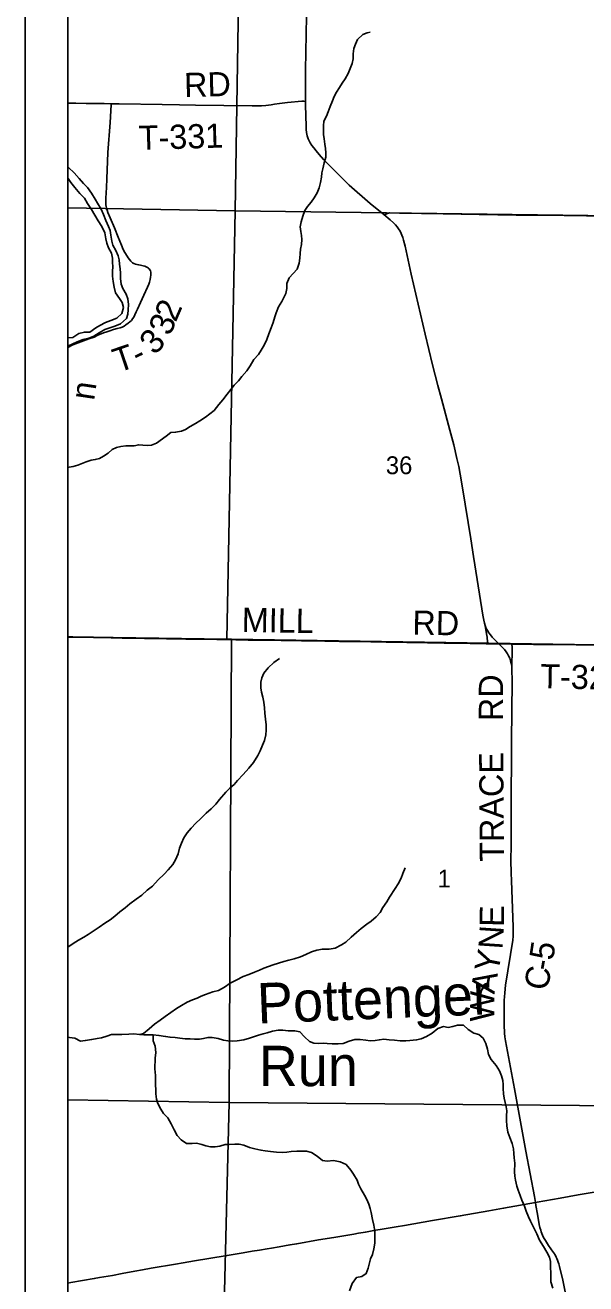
# Model space of a CAD drawing. Extents: x 0 to 34, y 0 to 22.
# Drawn here: x 2 to 3.317, y 16.874 to 19.83 of the extents above; entities that cross this region are included whole.
import ezdxf

# ---------------------------------------------------------------- set-up
doc = ezdxf.new("R2010")
doc.units = 0
for name, color, linetype in [('GM_X_Corporation', 7, 'Continuous'), ('GM_X_County_Road', 7, 'Continuous'), ('GM_X_County_Road_Text', 7, 'Continuous'), ('GM_X_Major_River', 7, 'Continuous'), ('GM_X_Minor_River', 7, 'Continuous'), ('GM_X_Minor_River_Text', 7, 'Continuous'), ('GM_X_Rail_Line_Text', 7, 'Continuous'), ('GM_X_Section_Text', 7, 'Continuous'), ('GM_X_State_Location', 7, 'Continuous'), ('GM_X_State_Route', 7, 'Continuous'), ('GM_X_Township_Road', 7, 'Continuous'), ('GM_X_Township_Road_Text', 7, 'Continuous'), ('SH_Data', 7, 'Continuous')]:
    doc.layers.add(name, color=color, linetype=linetype)

msp = doc.modelspace()

# ---------------------------------------------------------------- linework, layer by layer
at = {"layer": 'GM_X_Corporation'}
for points in [[(2.1, 20.9), (2.1, 18.3932), (2.1117, 18.393), (2.1602, 18.3922), (2.202, 18.3914), (2.2273, 18.3909), (2.2553, 18.3907), (2.2801, 18.3902), (2.3025, 18.3898), (2.3317, 18.3894), (2.377, 18.3886), (2.423, 18.388), (2.4497, 18.3877), (2.4944, 18.3869), (2.5236, 18.3864), (2.5653, 18.3858), (2.6013, 18.3852), (2.6162, 18.385), (2.6485, 18.3844), (2.7038, 18.3834), (2.738, 18.3831), (2.7746, 18.3825), (2.8113, 18.382), (2.8473, 18.3816), (2.9443, 18.38), (2.9834, 18.3794), (3.0068, 18.379), (3.0451, 18.3784), (3.0716, 18.3779), (3.0834, 18.3777), (3.0859, 18.3777), (3.0906, 18.3777), (3.0991, 18.3776), (3.1035, 18.3775), (3.1121, 18.3774), (3.1429, 18.3768), (3.1537, 18.3767), (3.1933, 18.3762), (3.2311, 18.3758), (3.3557, 18.374)], [(3.3557, 18.374), (3.2311, 18.3758), (3.1933, 18.3762), (3.1537, 18.3767), (3.1429, 18.3768), (3.1121, 18.3774), (3.1035, 18.3775), (3.0991, 18.3776), (3.0906, 18.3777), (3.0859, 18.3777), (3.0834, 18.3777), (3.0716, 18.3779), (3.0451, 18.3784), (3.0068, 18.379), (2.9834, 18.3794), (2.9443, 18.38), (2.8473, 18.3816), (2.8113, 18.382), (2.7746, 18.3825), (2.738, 18.3831), (2.7038, 18.3834), (2.6485, 18.3844), (2.6162, 18.385), (2.6013, 18.3852), (2.5653, 18.3858), (2.5236, 18.3864), (2.4944, 18.3869), (2.4497, 18.3877), (2.423, 18.388), (2.377, 18.3886), (2.3317, 18.3894), (2.3025, 18.3898), (2.2801, 18.3902), (2.2553, 18.3907), (2.2273, 18.3909), (2.202, 18.3914), (2.1602, 18.3922), (2.1117, 18.393), (2.1, 18.3932), (2.1, 14.1)]]:
    msp.add_lwpolyline(points, dxfattribs=at)
for points in [[(2.1, 20.3889), (2.1, 19.4012), (2.4933, 19.3936), (2.5086, 20.3801)], [(2.5086, 20.3801), (3.5147, 20.359), (3.4987, 19.3808), (2.4933, 19.3936)], [(2.1, 19.4012), (2.1, 18.3932), (2.4733, 18.3879), (2.4933, 19.3936)], [(3.4987, 19.3808), (3.4912, 18.3726), (2.4847, 18.3876), (2.4733, 18.3879), (2.4933, 19.3936)], [(2.1, 18.3932), (2.1, 17.3057), (2.4791, 17.2994), (2.4847, 18.3876), (2.4733, 18.3879)], [(2.4847, 18.3876), (3.4912, 18.3726), (3.4847, 17.2912), (2.4791, 17.2994)], [(2.1, 17.3057), (2.1, 16.3195), (2.4544, 16.3158), (2.4791, 17.2994)], [(3.4847, 17.2912), (3.4681, 16.2816), (2.4544, 16.3158), (2.4791, 17.2994)]]:
    msp.add_lwpolyline(points, close=True, dxfattribs=at)
at = {"layer": 'GM_X_County_Road'}
for points in [[(3.1124, 18.3769), (3.1011, 18.388), (3.0965, 18.3929), (3.0927, 18.3977), (3.0891, 18.4027), (3.0855, 18.4085), (3.0829, 18.4133), (3.0803, 18.4203), (3.0787, 18.4255), (3.077, 18.4327), (3.0749, 18.4442), (3.067, 18.4939), (3.0531, 18.5823), (3.0469, 18.6232), (3.027, 18.7437), (3.0214, 18.7754), (3.0183, 18.7933), (3.014, 18.8126), (3.0064, 18.8441), (2.9976, 18.879), (2.978, 18.9523), (2.9693, 18.9834), (2.9566, 19.0321), (2.9478, 19.0679), (2.939, 19.1045), (2.9063, 19.2455), (2.892, 19.311), (2.8885, 19.3249), (2.8866, 19.3316), (2.8847, 19.3369), (2.883, 19.3409), (2.8804, 19.3459), (2.8768, 19.3519), (2.8735, 19.3565), (2.8695, 19.3613), (2.8651, 19.3657), (2.8571, 19.3727), (2.842, 19.385), (2.8098, 19.4111), (2.7608, 19.454), (2.7006, 19.5149), (2.6907, 19.5261), (2.6835, 19.5346), (2.6777, 19.5419), (2.6734, 19.5478), (2.6693, 19.554), (2.6662, 19.56), (2.6648, 19.5633), (2.6624, 19.5703), (2.6607, 19.5781), (2.66, 19.5848), (2.6595, 19.5922), (2.6587, 19.6431), (2.6585, 19.6511), (2.6584, 19.6599), (2.6586, 19.7245), (2.6603, 19.8512)], [(2.1, 18.3927), (2.112, 18.3925), (2.1604, 18.3916), (2.2022, 18.3908), (2.2275, 18.3904), (2.2555, 18.3902), (2.2804, 18.3897), (2.3027, 18.3893), (2.3319, 18.3889), (2.3773, 18.3881), (2.4232, 18.3875), (2.4499, 18.3871), (2.4947, 18.3864), (2.5239, 18.3859), (2.5655, 18.3853), (2.6015, 18.3847), (2.6164, 18.3845), (2.6488, 18.3839), (2.704, 18.3829), (2.7382, 18.3826), (2.7749, 18.382), (2.8115, 18.3815), (2.8476, 18.3811), (2.9445, 18.3794), (2.9836, 18.3788), (3.007, 18.3785), (3.0453, 18.3778), (3.0718, 18.3774), (3.0826, 18.3772), (3.0861, 18.3772), (3.0908, 18.3771), (3.0993, 18.3771), (3.1124, 18.3769)], [(3.2703, 16.8429), (3.2623, 16.8819), (3.2545, 16.9144), (3.2531, 16.9203), (3.2517, 16.9248), (3.2503, 16.929), (3.2486, 16.9332), (3.2471, 16.9364), (3.2452, 16.9401), (3.2439, 16.9423), (3.2427, 16.9445), (3.2416, 16.9462), (3.2402, 16.9484), (3.2292, 16.9638), (3.2216, 16.9753), (3.2188, 16.9799), (3.2167, 16.9837), (3.2146, 16.9879), (3.2131, 16.9919), (3.2118, 16.9956), (3.2106, 16.9995), (3.209, 17.0062), (3.2074, 17.0127), (3.203, 17.0376), (3.1995, 17.0579), (3.1984, 17.0647), (3.196, 17.0787), (3.1755, 17.1856), (3.149, 17.3316), (3.1279, 17.4442), (3.1266, 17.4537), (3.1256, 17.4624), (3.125, 17.482), (3.1248, 17.5402), (3.1253, 17.5481), (3.1261, 17.5568), (3.1282, 17.575), (3.1452, 17.6807), (3.146, 17.6901), (3.1463, 17.6995), (3.146, 17.7112), (3.1452, 17.7342), (3.1419, 17.82), (3.1412, 17.8391), (3.1407, 17.8678), (3.1411, 17.9038), (3.1416, 17.9795), (3.1424, 18.149), (3.1434, 18.2887), (3.1432, 18.318), (3.1429, 18.3257), (3.1416, 18.3313), (3.14, 18.3366), (3.1379, 18.3431), (3.1354, 18.3484), (3.1325, 18.3536), (3.1295, 18.358), (3.1255, 18.3633), (3.1213, 18.3682), (3.1124, 18.3769)]]:
    msp.add_lwpolyline(points, dxfattribs=at)
at = {"layer": 'GM_X_Major_River'}
for points in [[(2.1782, 19.3978), (2.1702, 19.412), (2.1644, 19.4216), (2.1556, 19.4355), (2.1465, 19.449), (2.1369, 19.4584), (2.1269, 19.47), (2.1151, 19.4836), (2.1018, 19.496), (2.1, 19.4973)], [(2.1, 19.4711), (2.1011, 19.4699), (2.1073, 19.4602), (2.1165, 19.4486), (2.1283, 19.435), (2.1394, 19.4234), (2.1467, 19.4111), (2.1555, 19.3972), (2.1638, 19.3837), (2.1715, 19.3702), (2.1802, 19.3571), (2.1867, 19.3422), (2.1898, 19.328), (2.1914, 19.3178), (2.1953, 19.3074), (2.2026, 19.2947), (2.2049, 19.2829), (2.2054, 19.2726), (2.206, 19.2631), (2.2049, 19.2518), (2.205, 19.2404), (2.207, 19.2282), (2.2086, 19.2149), (2.212, 19.2011), (2.2219, 19.1884), (2.2281, 19.1788), (2.2309, 19.1669), (2.2271, 19.1526), (2.2151, 19.1419), (2.2009, 19.1365), (2.1887, 19.1315), (2.1756, 19.125), (2.166, 19.1192), (2.1521, 19.1093), (2.1392, 19.1092), (2.1262, 19.1057), (2.1119, 19.0962), (2.1, 19.0956)], [(2.1, 19.0756), (2.1, 19.0757), (2.1123, 19.0818), (2.1223, 19.0861), (2.1365, 19.0918), (2.1498, 19.0945), (2.1613, 19.0996), (2.1737, 19.1076), (2.1871, 19.1153), (2.2009, 19.1202), (2.2108, 19.1234), (2.2239, 19.1288), (2.2378, 19.1413), (2.2407, 19.1511), (2.2421, 19.1617), (2.2428, 19.1742), (2.2409, 19.1872), (2.2373, 19.1979), (2.2293, 19.2117), (2.2251, 19.2221), (2.2242, 19.2354), (2.2238, 19.2479), (2.2233, 19.2574), (2.2217, 19.2688), (2.2204, 19.2791), (2.2187, 19.2886), (2.2126, 19.3005), (2.2061, 19.3132), (2.2037, 19.3228), (2.2014, 19.3369), (2.1994, 19.3479), (2.1958, 19.3575), (2.1897, 19.3709), (2.184, 19.3851), (2.1782, 19.3978)]]:
    msp.add_lwpolyline(points, dxfattribs=at)
at = {"layer": 'GM_X_Minor_River'}
for points in [[(2.6957, 19.473), (2.697, 19.4829), (2.6991, 19.4927), (2.7024, 19.5067), (2.7057, 19.5203), (2.7062, 19.5305), (2.7049, 19.54), (2.704, 19.5503), (2.7023, 19.5632), (2.7006, 19.5735), (2.7004, 19.5837), (2.7006, 19.594), (2.7015, 19.6042), (2.7078, 19.6162), (2.7118, 19.6268), (2.7166, 19.6388), (2.7218, 19.6524), (2.7258, 19.6622), (2.7313, 19.6727), (2.7383, 19.684), (2.7445, 19.6937), (2.7516, 19.7039), (2.7586, 19.7166), (2.7634, 19.7283), (2.7678, 19.7404), (2.7699, 19.7513), (2.7705, 19.7627), (2.7722, 19.7756), (2.7758, 19.7858), (2.7802, 19.7967), (2.7929, 19.8082), (2.8033, 19.8118), (2.8101, 19.8136)], [(2.1, 18.791), (2.1034, 18.7917), (2.1129, 18.7931), (2.124, 18.7967), (2.1431, 18.8043), (2.1549, 18.8086), (2.1644, 18.8096), (2.1747, 18.8124), (2.1843, 18.8176), (2.1947, 18.8246), (2.2043, 18.8331), (2.2143, 18.8382), (2.2249, 18.8403), (2.236, 18.8416), (2.2458, 18.8418), (2.2557, 18.8416), (2.2668, 18.8445), (2.2762, 18.8439), (2.2872, 18.8426), (2.2967, 18.8432), (2.3082, 18.8479), (2.3313, 18.8649), (2.3424, 18.8734), (2.3534, 18.874), (2.3668, 18.8764), (2.3763, 18.8804), (2.3878, 18.8874), (2.4001, 18.8947), (2.4105, 18.9006), (2.4235, 18.9091), (2.4339, 18.9169), (2.4435, 18.925), (2.4544, 18.9392), (2.4645, 18.9504), (2.4746, 18.9635), (2.4828, 18.974), (2.4905, 18.9841), (2.5006, 18.9949), (2.5087, 19.0046), (2.5204, 19.018), (2.5286, 19.03), (2.5372, 19.0447), (2.5476, 19.0566), (2.5543, 19.0663), (2.5613, 19.0787), (2.5676, 19.0915), (2.5721, 19.1047), (2.578, 19.119), (2.5824, 19.1318), (2.5861, 19.1446), (2.5893, 19.1544), (2.5952, 19.1684), (2.6027, 19.1811), (2.6121, 19.1995), (2.6142, 19.2116), (2.6148, 19.2234), (2.62, 19.2362), (2.6297, 19.2466), (2.639, 19.2567), (2.6434, 19.271), (2.6448, 19.2831), (2.6457, 19.2941), (2.6467, 19.304), (2.6491, 19.3145), (2.6501, 19.3267), (2.6488, 19.3362), (2.6471, 19.3457), (2.6457, 19.3563), (2.6482, 19.3684), (2.6523, 19.3816), (2.6571, 19.3944), (2.6633, 19.4042), (2.6715, 19.4147), (2.6785, 19.4248), (2.6859, 19.4364), (2.6903, 19.4481), (2.6932, 19.4606), (2.6957, 19.473)], [(2.1, 17.664), (2.1005, 17.6643), (2.1125, 17.6728), (2.1256, 17.6812), (2.1379, 17.6877), (2.1479, 17.6939), (2.1599, 17.7019), (2.1738, 17.7115), (2.1873, 17.7206), (2.1993, 17.729), (2.2105, 17.7375), (2.2225, 17.7471), (2.2345, 17.757), (2.2457, 17.7666), (2.2608, 17.7772), (2.2743, 17.7864), (2.2867, 17.7982), (2.2987, 17.8074), (2.3123, 17.8222), (2.3267, 17.8359), (2.3357, 17.8459), (2.3466, 17.8589), (2.3533, 17.8698), (2.359, 17.884), (2.3627, 17.8972), (2.3672, 17.9089), (2.3728, 17.9216), (2.3807, 17.9332), (2.3901, 17.944), (2.401, 17.9555), (2.4119, 17.9658), (2.4251, 17.9795), (2.4371, 17.9895), (2.4476, 18.0002), (2.4566, 18.0114), (2.4711, 18.0285), (2.4808, 18.0377), (2.4905, 18.0462), (2.4987, 18.0558), (2.5116, 18.0699), (2.5256, 18.0848), (2.5362, 18.0982), (2.5461, 18.115), (2.552, 18.1255), (2.5577, 18.139), (2.5621, 18.1499), (2.5655, 18.1631), (2.5661, 18.174), (2.5657, 18.1869), (2.5645, 18.2002), (2.5629, 18.2143), (2.5621, 18.2265), (2.5605, 18.2398), (2.5578, 18.252), (2.5551, 18.2631), (2.5538, 18.2737), (2.5534, 18.287), (2.5555, 18.2968), (2.5607, 18.3081), (2.5709, 18.3207), (2.5841, 18.3333), (2.5972, 18.3428)], [(2.2688, 17.4596), (2.2779, 17.4616), (2.2911, 17.4723), (2.3035, 17.4834), (2.317, 17.4933), (2.329, 17.5014), (2.3421, 17.5113), (2.3553, 17.5204), (2.3672, 17.5277), (2.3803, 17.535), (2.3929, 17.5411), (2.4037, 17.545), (2.4136, 17.5493), (2.4236, 17.5529), (2.4404, 17.5593), (2.4542, 17.5628), (2.468, 17.5708), (2.4811, 17.5799), (2.4954, 17.5872), (2.5123, 17.5955), (2.5249, 17.6001), (2.5383, 17.6055), (2.5502, 17.6105), (2.5605, 17.6148), (2.5716, 17.619), (2.5827, 17.6226), (2.5946, 17.6268), (2.6072, 17.6311), (2.619, 17.6338), (2.632, 17.6373), (2.6465, 17.6419), (2.6592, 17.6472), (2.6723, 17.6538), (2.6849, 17.6576), (2.6982, 17.6599), (2.7141, 17.6599), (2.7278, 17.6619), (2.7428, 17.6702), (2.7532, 17.676), (2.7657, 17.6879), (2.7784, 17.6989), (2.7893, 17.7082), (2.8024, 17.7185), (2.8125, 17.7254), (2.8241, 17.7357), (2.8338, 17.7457), (2.8402, 17.7577), (2.8497, 17.7711), (2.8556, 17.782), (2.869, 17.8022), (2.8757, 17.8134), (2.8829, 17.8268), (2.8866, 17.8374), (2.8926, 17.8505)], [(2.4187, 17.4502), (2.4287, 17.4519), (2.4389, 17.452), (2.4533, 17.4498), (2.4661, 17.446), (2.4759, 17.4447), (2.4861, 17.444), (2.4975, 17.4445), (2.5135, 17.4464), (2.5272, 17.451), (2.5383, 17.4549), (2.5479, 17.4577), (2.5586, 17.4605), (2.5685, 17.4632), (2.5811, 17.4671), (2.5945, 17.4691), (2.6051, 17.4692), (2.6179, 17.4677), (2.6331, 17.4681), (2.6452, 17.4659), (2.6559, 17.4535), (2.6674, 17.4426), (2.6779, 17.439), (2.6881, 17.4383), (2.6995, 17.4388), (2.7094, 17.4382), (2.7207, 17.4375), (2.7351, 17.4372), (2.7465, 17.4384), (2.7611, 17.4437), (2.7745, 17.4476), (2.787, 17.4477), (2.7998, 17.4462), (2.8104, 17.4444), (2.8218, 17.4449), (2.8321, 17.4469), (2.842, 17.4482), (2.8545, 17.4471), (2.8673, 17.4457), (2.881, 17.4446), (2.8939, 17.4443), (2.9037, 17.4452), (2.9193, 17.4467), (2.9296, 17.4491), (2.9423, 17.4549), (2.9558, 17.4625), (2.9693, 17.4732), (2.9827, 17.4778), (2.9936, 17.476), (3.0043, 17.4784), (3.0154, 17.4815), (3.0294, 17.4812), (3.0402, 17.471), (3.0536, 17.4624), (3.0653, 17.4594), (3.0753, 17.4508), (3.0822, 17.4382), (3.0861, 17.4248), (3.0884, 17.4126), (3.0942, 17.4007), (3.106, 17.3868), (3.114, 17.3737), (3.1186, 17.3622), (3.1214, 17.3515), (3.1223, 17.3416), (3.1228, 17.3321), (3.1233, 17.32), (3.1249, 17.3097), (3.1269, 17.2998), (3.1293, 17.2895), (3.1314, 17.2799), (3.1303, 17.2686), (3.1304, 17.2576), (3.1313, 17.245), (3.1332, 17.2302), (3.1378, 17.2172), (3.1439, 17.203), (3.1466, 17.1908), (3.1475, 17.1798), (3.1487, 17.1695), (3.1499, 17.1574), (3.1494, 17.1369), (3.1499, 17.1266), (3.1516, 17.1171), (3.1543, 17.1034), (3.1578, 17.0938), (3.1621, 17.0808), (3.166, 17.0701), (3.1725, 17.0559), (3.1763, 17.0445), (3.1821, 17.031), (3.1864, 17.0211), (3.194, 17.0069), (3.2016, 16.9911), (3.208, 16.9766), (3.2175, 16.9615), (3.2251, 16.9481), (3.2313, 16.9362), (3.2333, 16.9259), (3.2337, 16.9122), (3.2342, 16.8997)], [(2.1, 17.4527), (2.104, 17.4522), (2.1168, 17.4504), (2.1303, 17.4436), (2.141, 17.4449), (2.1562, 17.4479), (2.1688, 17.4499), (2.1791, 17.4515), (2.1921, 17.4554), (2.2028, 17.4593), (2.2168, 17.4593), (2.2267, 17.4595), (2.2438, 17.4602), (2.2548, 17.4611), (2.2688, 17.4596), (2.279, 17.4586), (2.2889, 17.4587), (2.3006, 17.4588), (2.3142, 17.4573), (2.3297, 17.4547), (2.3403, 17.4529), (2.3524, 17.4519), (2.3634, 17.4504), (2.3755, 17.4494), (2.3872, 17.4495), (2.3975, 17.4485), (2.4092, 17.4482), (2.4187, 17.4502)], [(2.3006, 17.4588), (2.3007, 17.4448), (2.3053, 17.4321), (2.3068, 17.4169), (2.3053, 17.4037), (2.3047, 17.3783), (2.3058, 17.3627), (2.3063, 17.3532), (2.3064, 17.3407), (2.3065, 17.3297), (2.307, 17.3198), (2.3086, 17.3077), (2.3114, 17.297), (2.3183, 17.2839), (2.3252, 17.2735), (2.3348, 17.2634), (2.3428, 17.2492), (2.35, 17.235), (2.3566, 17.2219), (2.3662, 17.2118), (2.3792, 17.2035), (2.3921, 17.2032), (2.4024, 17.2037), (2.4148, 17.2012), (2.4246, 17.1979), (2.4355, 17.1957), (2.4458, 17.1951), (2.4568, 17.1971), (2.4698, 17.2006), (2.4793, 17.2011), (2.4922, 17.2015), (2.5028, 17.2017), (2.5138, 17.1991), (2.5269, 17.1942), (2.5397, 17.1905), (2.5537, 17.1879), (2.5639, 17.1857), (2.5764, 17.1843), (2.59, 17.1828), (2.6036, 17.1821), (2.6142, 17.1826), (2.6249, 17.1843), (2.6378, 17.1855), (2.6507, 17.1855), (2.661, 17.1849), (2.6723, 17.182), (2.6857, 17.1737), (2.6984, 17.1635), (2.7093, 17.1621), (2.7241, 17.1632), (2.74, 17.1606), (2.7535, 17.1538), (2.7649, 17.141), (2.7711, 17.1314), (2.7795, 17.1175), (2.7831, 17.1076), (2.7885, 17.0968), (2.7972, 17.0818), (2.8026, 17.0714), (2.8069, 17.0611), (2.8101, 17.0508), (2.8125, 17.0412), (2.8159, 17.0245), (2.8186, 17.0111), (2.8209, 16.997), (2.8213, 16.983), (2.821, 16.969), (2.8187, 16.9557), (2.8154, 16.9429), (2.8109, 16.9324), (2.8084, 16.9226), (2.8055, 16.9102), (2.801, 16.8978), (2.791, 16.8912), (2.778, 16.8885), (2.7678, 16.8743), (2.762, 16.857)], [(3.2342, 16.8997), (3.2347, 16.8898), (3.2344, 16.8784), (3.2394, 16.8635)]]:
    msp.add_lwpolyline(points, dxfattribs=at)
at = {"layer": 'GM_X_State_Route'}
msp.add_lwpolyline([(2.1, 16.8755), (2.1076, 16.8768), (2.1621, 16.886), (2.1743, 16.8882), (2.2048, 16.8936), (2.2281, 16.898), (2.2574, 16.9032), (2.2758, 16.9065), (2.296, 16.9101), (2.353, 16.9196), (2.3713, 16.9228), (2.3977, 16.9273), (2.4699, 16.9396), (2.5122, 16.9467), (2.533, 16.9503), (2.5502, 16.9531), (2.5686, 16.9562), (2.5784, 16.9578), (2.5968, 16.9608), (2.6219, 16.965), (2.6378, 16.9678), (2.6892, 16.9768), (2.7248, 16.9827), (2.7719, 16.9906), (2.7829, 16.9926), (2.7989, 16.9953), (2.8185, 16.9986), (2.843, 17.0026), (2.8712, 17.0073), (2.8908, 17.0107), (2.9563, 17.0221), (3.0218, 17.0332), (3.0891, 17.0452), (3.1234, 17.051), (3.1984, 17.0647), (3.2023, 17.0654), (3.2561, 17.075), (3.2983, 17.0826), (3.3412, 17.0896)], dxfattribs=at)
at = {"layer": 'GM_X_Township_Road'}
for points in [[(2.1, 19.647), (2.1189, 19.6467), (2.1431, 19.6463), (2.1853, 19.6459), (2.2021, 19.6456), (2.2207, 19.6455), (2.3219, 19.6435), (2.3628, 19.6431), (2.4, 19.6422), (2.5328, 19.6403), (2.5459, 19.6405), (2.5546, 19.6408), (2.5651, 19.6416), (2.5775, 19.6431), (2.5855, 19.6442), (2.5972, 19.6459), (2.6162, 19.6484), (2.6501, 19.6514), (2.6546, 19.6514), (2.6585, 19.6511)], [(2.1, 19.0728), (2.1122, 19.079), (2.1496, 19.0936), (2.1618, 19.0974), (2.171, 19.1017), (2.1842, 19.1071), (2.1918, 19.1099), (2.199, 19.1124), (2.2071, 19.1149), (2.216, 19.1173), (2.2231, 19.1192), (2.2278, 19.1208), (2.2322, 19.1231), (2.2366, 19.126), (2.2422, 19.1302), (2.2461, 19.1333), (2.2498, 19.1367), (2.2524, 19.14), (2.2549, 19.1442), (2.2576, 19.1493), (2.2608, 19.1567), (2.2636, 19.163), (2.2706, 19.1788), (2.2786, 19.1961), (2.287, 19.2146), (2.2901, 19.2214), (2.292, 19.2265), (2.2936, 19.2325), (2.2947, 19.2378), (2.2951, 19.2431), (2.2951, 19.2463), (2.2948, 19.2496), (2.2941, 19.253), (2.293, 19.2556), (2.2915, 19.2578), (2.2898, 19.2594), (2.2872, 19.2612), (2.2841, 19.2627), (2.2809, 19.2638), (2.277, 19.2649), (2.2711, 19.2661), (2.2666, 19.2668), (2.2629, 19.2676), (2.2591, 19.2685), (2.2554, 19.2702), (2.2522, 19.2722), (2.2484, 19.2756), (2.2449, 19.2793), (2.2415, 19.2834), (2.2392, 19.2873), (2.234, 19.2958), (2.2301, 19.3035), (2.226, 19.313), (2.2184, 19.3321), (2.21, 19.3538), (2.1994, 19.3778), (2.1941, 19.3904), (2.1922, 19.3955), (2.1907, 19.4011), (2.1899, 19.4043), (2.1896, 19.4077), (2.1896, 19.4107), (2.1898, 19.4235), (2.1909, 19.4491), (2.1917, 19.4689), (2.1945, 19.5313), (2.1995, 19.6015), (2.2019, 19.643), (2.2021, 19.6456)], [(2.842, 19.385), (2.8468, 19.3865), (2.8511, 19.3878), (2.8558, 19.3889), (2.8794, 19.3883), (2.9819, 19.3867), (3.0658, 19.3854), (3.1527, 19.3839), (3.2136, 19.3834), (3.318, 19.3825), (3.4012, 19.3812), (3.4391, 19.3807), (3.4702, 19.3801), (3.5031, 19.3798)], [(3.0861, 18.3772), (3.0857, 18.381), (3.0846, 18.3923), (3.0836, 18.4002), (3.0803, 18.4203)], [(3.1124, 18.3769), (3.1431, 18.3763), (3.1539, 18.3762), (3.1935, 18.3757), (3.2314, 18.3752), (3.3559, 18.3734), (3.395, 18.3729), (3.4846, 18.3714)], [(3.1429, 18.3257), (3.1432, 18.341), (3.1436, 18.3453), (3.1436, 18.3595), (3.1433, 18.3694), (3.1431, 18.3763)]]:
    msp.add_lwpolyline(points, dxfattribs=at)
at = {"layer": 'SH_Data'}
for p, q in [((2, 21), (2, 14)), ((2.1, 20.9), (2.1, 14.1)), ((2.1, 20.9), (2.1, 14.1)), ((2.1, 20.9), (2.1, 14.1))]:
    msp.add_line(p, q, dxfattribs=at)

# ---------------------------------------------------------------- texts
at = {"layer": 'GM_X_County_Road_Text'}
for s, height, rotation, p in [('MILL', 0.05682, 358.9293, (2.5082, 18.4052)), ('RD', 0.05682, 359.0128, (2.909, 18.3985)), ('RD', 0.05682, 90, (3.1222, 18.1953)), ('TRACE', 0.05682, 90.4049, (3.1246, 17.8652)), ('E', 0.0568, 89.5264, (3.1242, 17.712)), ('N', 0.0568, 86.1674, (3.1207, 17.6585)), ('Y', 0.0568, 79.0478, (3.1102, 17.6018)), ('5', 0.0568, 81.4671, (3.2397, 17.6315)), ('-', 0.0568, 79.6877, (3.2352, 17.6066)), ('A', 0.0568, 80.3799, (3.1019, 17.5528)), ('C', 0.0568, 79.3508, (3.2265, 17.5604)), ('W', 0.0568, 89.2924, (3.1013, 17.4893))]:
    msp.add_text(s, height=height, rotation=rotation, dxfattribs=at).set_placement(p)
at = {"layer": 'GM_X_Minor_River_Text'}
for s, rotation, p in [('Pottenger', 2.314, (2.5464, 17.485)), ('Run', 0.0019, (2.5489, 17.338))]:
    msp.add_text(s, height=0.09469, rotation=rotation, dxfattribs=at).set_placement(p)
at = {"layer": 'GM_X_Rail_Line_Text'}
msp.add_text('n', height=0.0566, rotation=81.5004, dxfattribs=at).set_placement((2.1617, 18.9471))
at = {"layer": 'GM_X_Section_Text'}
for s, height, p in [('36', 0.04186, (2.847, 18.7754)), ('1', 0.0419, (2.9687, 17.8046))]:
    msp.add_text(s, height=height, rotation=0, dxfattribs=at).set_placement(p)
at = {"layer": 'GM_X_State_Location'}
msp.add_text('725', height=0.000189, rotation=0, dxfattribs=at).set_placement((2.9687, 17.0006))
for s in ['s', 'r']:
    msp.add_text(s, height=0.000189, dxfattribs=at).set_placement((3.0355, 17.0144))
at = {"layer": 'GM_X_Township_Road_Text'}
for s, height, rotation, p in [('RD', 0.05682, 1.4825, (2.3739, 19.661)), ('T-331', 0.05682, 1.6848, (2.2674, 19.5368)), ('2', 0.0568, 66.4618, (2.3535, 19.1305)), ('3', 0.0568, 68.4727, (2.3408, 19.0984)), ('3', 0.0568, 46.5611, (2.3041, 19.0532)), ('T', 0.0568, 18.7663, (2.2178, 19.0133)), ('-', 0.0568, 25.6123, (2.2649, 19.0298)), ('T-328', 0.05682, 358.8768, (3.2092, 18.2726))]:
    msp.add_text(s, height=height, rotation=rotation, dxfattribs=at).set_placement(p)

doc.saveas('drawing.dxf')
